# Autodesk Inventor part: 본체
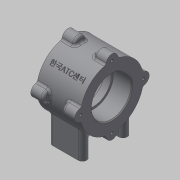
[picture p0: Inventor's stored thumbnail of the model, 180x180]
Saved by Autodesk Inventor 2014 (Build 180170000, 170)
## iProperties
Created: 2015-03
Part Number: 본체
Material: Generic
Document SubType Name: Modeling
Designer: MYHOME
Density: 1 g/cm^3
Appearance: Default
Author: MYHOME
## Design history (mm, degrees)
sketch "스케치2"
  geometry: C1 r 37 at (0, 0); 1 further point
  constraints: 1 centre point, 1 coincident
  dimensions: "d0" = 74 diameter of C1
extrude "돌출1" new body sketch "스케치2" stored distance "d1" = 52; taper "d2" = 0 deg
node "작업 평면1"
sketch "스케치3"
  geometry: L1 (-15, -24)-(15, -24); L2 (-15, -29)-(15, -29); L3 (15, -19)-(-15, -19); L4 (-15, 24)-(15, 24); L5 (-15, 19)-(15, 19); L6 (15, 29)-(-15, 29); A1 r 5 centre (-15, -24) between (-15, -19) and (-15, -29); A2 r 5 centre (15, -24) between (15, -29) and (15, -19); A3 r 5 centre (-15, 24) between (-15, 29) and (-15, 19); A4 r 5 centre (15, 24) between (15, 19) and (15, 29); 3 further points
  constraints: 16 end point, 8 point on circle, 8 tangent, 4 centre point, 3 parallel, 2 midpoint, 2 vertical alignment, 1 horizontal
  dimensions: "d4" = 10 distance between parallel lines of L3 L2; "d5" = 10 distance between parallel lines of L6 L5; "d6" = 40 dimension on A4 A3; "d7" = 40 dimension on A2 A1; "d8" = 48 distance of L4.start L1.start; "d9" = 24 distance of point (0, 0) point (0, -24)
extrude "돌출2" join sketch "스케치3" stored distance "d10" = 10; taper "d11" = 0 deg
sketch "스케치4"
  geometry: C1 r 7 at (0, 37); C2 r 7 at (-37, 0); C3 r 7 at (37, 0); C4 r 7 at (0, -37); A1 r 37 centre (0, 0) between (0, 37) and (-37, 0) reference
  constraints: 4 centre point, 4 point on circle, 2 horizontal alignment, 2 vertical alignment
  dimensions: "d12" = 14 diameter of C1; "d13" = 14 diameter of C2; "d14" = 14 diameter of C3; "d15" = 14 diameter of C4
extrude "돌출3" join sketch "스케치4" distance "d16" = 15; taper "d17" = 0 deg
sketch "스케치5"
  geometry: A1 r 7 centre (37, 0) between (36.338, -6.969) and (36.338, 6.969) reference; A2 r 7 centre (0, 37) between (6.969, 36.338) and (-6.969, 36.338) reference; A3 r 7 centre (-37, 0) between (-36.338, 6.969) and (-36.338, -6.969) reference; A4 r 7 centre (0, -37) between (-6.969, -36.338) and (6.969, -36.338) reference; 4 further points
  constraints: 4 coincident
hole "구멍1" sketch "스케치5" at (0, 37), (-37, 0), (37, 0), (0, -37) diameter "d18" = 3.242; stored, may be unused: countersink angle "d22" = 90 deg, drill point angle "d24" = 118 deg; dims "d19" = 8, "d20" = 4, "d21" = 2, "d23" = 11
sketch "스케치6"
  geometry: C1 r 23.5 at (0, 0); A1 r 37 centre (0, 0) between (-36.338, -6.969) and (-6.969, -36.338) reference
  constraints: 1 centre point, 1 coincident
  dimensions: "d25" = 47 diameter of C1
extrude "돌출4" cut sketch "스케치6" distance "d26" = 22; taper "d27" = 0 deg
sketch "스케치7"
  geometry: C1 r 23.5 at (0, 0); A1 r 37 centre (0, 0) between (-36.338, -6.969) and (-6.969, -36.338) reference
  constraints: 1 centre point, 1 coincident
  dimensions: "d28" = 47 diameter of C1
extrude "돌출5" cut sketch "스케치7" distance "d29" = 22; taper "d30" = 0 deg
sketch "스케치8"
  geometry: C1 r 23.5 at (0, 0) reference; C2 r 21 at (0, 0)
  constraints: 1 centre point, 1 coincident
  dimensions: "d31" = 42 diameter of C2
extrude "돌출6" cut sketch "스케치8" stored distance "d32" = 22; taper "d33" = 0 deg
chamfer "모따기1" distance "d34" = 1; stored, may be unused: second distance "d35" = 2, angle "d36" = 45 deg
fillet "모깎기1" dims "d37" = 0.3
sketch "스케치9"
  geometry: L1 (-15, 19)-(15, 19) reference; L2 (15, 29)-(-15, 29) reference; A1 r 5 centre (15, -24) between (15, -29) and (15, -19) reference; A2 r 5 centre (-15, -24) between (-15, -19) and (-15, -29) reference; A3 r 5 centre (15, 24) between (15, 19) and (15, 29) reference; A4 r 5 centre (-15, 24) between (-15, 29) and (-15, 19) reference; 5 further points
  constraints: 4 coincident
hole "구멍2" sketch "스케치9" at (-15, 24), (15, 24), (-15, -24), (15, -24) diameter "d38" = 4.134; stored, may be unused: countersink angle "d42" = 90 deg, drill point angle "d44" = 118 deg; dims "d39" = 6, "d40" = 4, "d41" = 2, "d43" = 8
sketch "스케치10"
  geometry: L1 (0, 0)-(-26.163, 26.163); L2 (0, 0)-(-37, 0); A1 r 37 centre (0, 0) between (-6.969, 36.338) and (-36.338, 6.969) reference; A2 r 37 centre (0, 0) between (-36.338, 6.969) and (-36.338, -6.969) reference; 2 further points
  constraints: 4 end point, 2 point on circle, 1 coincident
  dimensions: "d45" = 45 deg angle of L2 L1
node "작업 평면2"
sketch "스케치11"
  geometry: 3 further points
  constraints: 1 coincident, 1 other
feature "엠보싱1" sketch "스케치11" dims "d46" = 0.5, "d47" = 0
fillet "모깎기2" dims "d48" = 3
fillet "모깎기3" dims "d49" = 3
fillet "모깎기4" dims "d50" = 3
node "솔리드1"
mirror "대칭1"
node "투영된 루프1"
other parameters: "d3" = -56
